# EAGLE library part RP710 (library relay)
RELAY 2 x switch, Schrack
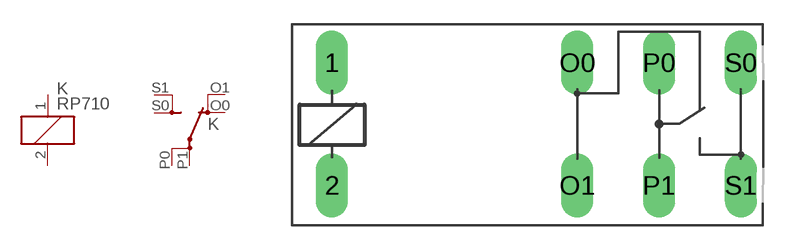
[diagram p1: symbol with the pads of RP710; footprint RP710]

Designator prefix K; gates 1=K 2=UD

## RP710 (MF: TYCO ELECTRONICS; MPN: RP710024; OC_FARNELL: 388312; OC_NEWARK: 17M1785)  [RP710]
1  1:1  pas
2  1:2  pas
O0  2:O  pas
O1  2:O  pas
P0  2:P  pas
P1  2:P  pas
S0  2:S  pas
S1  2:S  pas

## Footprint RP710 (pad centres in mm)
RELAY 2 x switch, Schrack
drill 1.321 long: 1 -3.81,3.81; 2 -3.81,-3.81; O0 11.43,3.81; O1 11.43,-3.81; P0 16.51,3.81; P1 16.51,-3.81; S0 21.59,3.81; S1 21.59,-3.81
